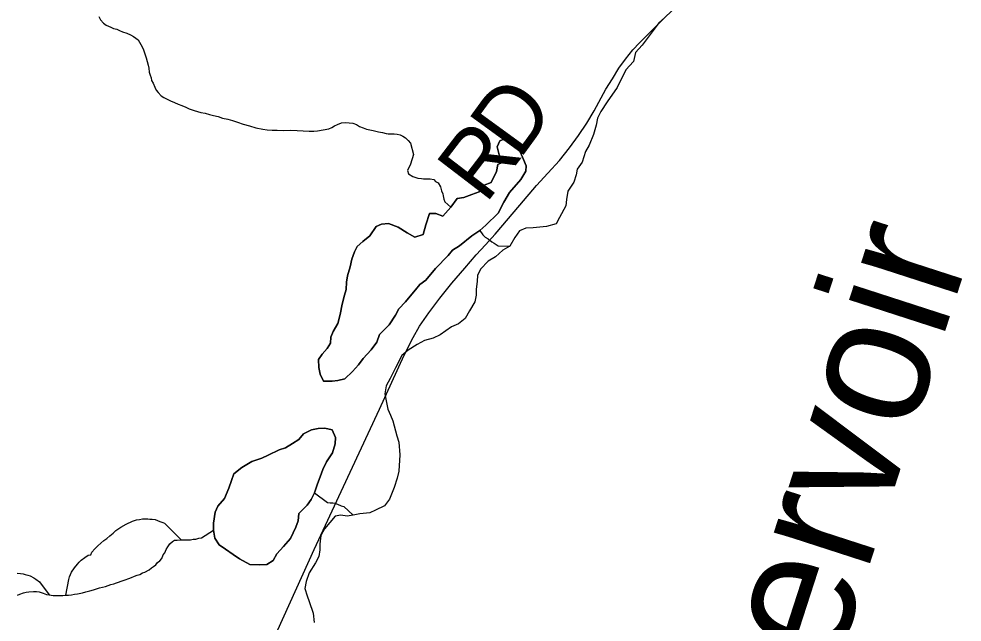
# Model space of a CAD drawing. Extents: x -10.1 to 68, y -9.5 to 29.2.
# Drawn here: x 5.518 to 6.333, y 19.95 to 20.471 of the extents above; entities that cross this region are included whole.
import ezdxf

# ---------------------------------------------------------------- set-up
doc = ezdxf.new("R2010")
doc.units = 0
for name, color, linetype in [('GM_X_Major_Lake', 7, 'Continuous'), ('GM_X_Major_Lake_Text', 7, 'Continuous'), ('GM_X_Major_River', 7, 'Continuous'), ('GM_X_Minor_Lake', 7, 'Continuous'), ('GM_X_Minor_River', 7, 'Continuous'), ('GM_X_Township_Road', 7, 'Continuous'), ('GM_X_Township_Road_Text', 7, 'Continuous')]:
    doc.layers.add(name, color=color, linetype=linetype)

msp = doc.modelspace()

# ---------------------------------------------------------------- linework, layer by layer
at = {"layer": 'GM_X_Major_Lake'}
for points in [[(6.07557, 20.47208), (6.07064, 20.4679), (6.06646, 20.46219), (6.05621, 20.44851), (6.05052, 20.44204), (6.04862, 20.43444), (6.04217, 20.42722), (6.03458, 20.41201), (6.02585, 20.39947), (6.02054, 20.3911), (6.0175, 20.3854), (6.01636, 20.37932), (6.01408, 20.37134), (6.01028, 20.36222), (6.00725, 20.35651), (6.00421, 20.34739), (6.00003, 20.34131), (5.99927, 20.33637), (5.997, 20.33029), (5.99206, 20.32231), (5.99092, 20.31509), (5.99016, 20.30977), (5.98485, 20.29951), (5.98181, 20.29418), (5.97346, 20.29189), (5.96777, 20.29113), (5.96208, 20.29074), (5.95563, 20.29035), (5.95032, 20.28807), (5.94614, 20.28236), (5.94197, 20.27476), (5.9359, 20.27133), (5.92945, 20.26563), (5.923, 20.26182), (5.91654, 20.25498), (5.91389, 20.24965), (5.91351, 20.24472), (5.91275, 20.2375), (5.91274, 20.23256), (5.9116, 20.22686), (5.90705, 20.21888), (5.90325, 20.21241), (5.89756, 20.20785), (5.89149, 20.20518), (5.88162, 20.19833), (5.87555, 20.19529), (5.86796, 20.19338), (5.86189, 20.18995), (5.85392, 20.18501), (5.84861, 20.18044), (5.84292, 20.16979), (5.83836, 20.16067), (5.83495, 20.15421), (5.83381, 20.14737), (5.83494, 20.14129), (5.83646, 20.13408), (5.83874, 20.12876), (5.84063, 20.12383), (5.84404, 20.11091), (5.84594, 20.1056), (5.84669, 20.09458), (5.84593, 20.08053), (5.84441, 20.07445), (5.84175, 20.06647), (5.83796, 20.0562), (5.8334, 20.0505), (5.82581, 20.04669), (5.82088, 20.04441), (5.81215, 20.04364), (5.80646, 20.04249), (5.80115, 20.04173), (5.79584, 20.04248), (5.79091, 20.04171), (5.7818, 20.03069), (5.77838, 20.02498), (5.77762, 20.01739), (5.77762, 20.01245), (5.77686, 20.00675), (5.77382, 20.00143), (5.76851, 19.99268), (5.76585, 19.98508), (5.76471, 19.979), (5.76661, 19.97293), (5.7685, 19.96799), (5.77192, 19.95774)], [(5.77192, 19.95774), (5.77267, 19.94976)]]:
    msp.add_lwpolyline(points, dxfattribs=at)
at = {"layer": 'GM_X_Major_River'}
for points in [[(6.07557, 20.47208), (6.07064, 20.4679), (6.06646, 20.46219), (6.05621, 20.44851), (6.05052, 20.44204), (6.04862, 20.43444), (6.04217, 20.42722), (6.03458, 20.41201), (6.02585, 20.39947), (6.02054, 20.3911), (6.0175, 20.3854), (6.01636, 20.37932), (6.01408, 20.37134), (6.01028, 20.36222), (6.00725, 20.35651), (6.00421, 20.34739), (6.00003, 20.34131), (5.99927, 20.33637), (5.997, 20.33029), (5.99206, 20.32231), (5.99092, 20.31509), (5.99016, 20.30977), (5.98485, 20.29951), (5.98181, 20.29418), (5.97346, 20.29189), (5.96777, 20.29113), (5.96208, 20.29074), (5.95563, 20.29035), (5.95032, 20.28807), (5.94614, 20.28236), (5.94197, 20.27476), (5.9359, 20.27133), (5.92945, 20.26563), (5.923, 20.26182), (5.91654, 20.25498), (5.91389, 20.24965), (5.91351, 20.24472), (5.91275, 20.2375), (5.91274, 20.23256), (5.9116, 20.22686), (5.90705, 20.21888), (5.90325, 20.21241), (5.89756, 20.20785), (5.89149, 20.20518), (5.88162, 20.19833), (5.87555, 20.19529), (5.86796, 20.19338), (5.86189, 20.18995), (5.85392, 20.18501), (5.84861, 20.18044), (5.84292, 20.16979), (5.83836, 20.16067), (5.83495, 20.15421), (5.83381, 20.14737), (5.83494, 20.14129), (5.83646, 20.13408), (5.83874, 20.12876), (5.84063, 20.12383), (5.84404, 20.11091), (5.84594, 20.1056), (5.84669, 20.09458), (5.84593, 20.08053), (5.84441, 20.07445), (5.84175, 20.06647), (5.83796, 20.0562), (5.8334, 20.0505), (5.82581, 20.04669), (5.82088, 20.04441), (5.81215, 20.04364), (5.80646, 20.04249), (5.80115, 20.04173), (5.79584, 20.04248), (5.79091, 20.04171), (5.7818, 20.03069), (5.77838, 20.02498), (5.77762, 20.01739), (5.77762, 20.01245), (5.77686, 20.00675), (5.77382, 20.00143), (5.76851, 19.99268), (5.76585, 19.98508), (5.76471, 19.979), (5.76661, 19.97293), (5.7685, 19.96799), (5.77192, 19.95774)], [(5.77192, 19.95774), (5.77267, 19.94976)]]:
    msp.add_lwpolyline(points, dxfattribs=at)
at = {"layer": 'GM_X_Minor_Lake'}
for points in [[(5.90896, 20.28384), (5.89834, 20.27509), (5.89227, 20.27128), (5.88847, 20.26672), (5.87746, 20.25569), (5.86912, 20.24542), (5.86418, 20.24162), (5.86039, 20.23706), (5.85583, 20.23173), (5.85166, 20.22679), (5.84596, 20.2207), (5.84293, 20.21538), (5.83761, 20.20702), (5.82927, 20.19865), (5.82699, 20.19181), (5.82205, 20.18535), (5.81522, 20.17774), (5.81105, 20.17242), (5.80574, 20.16671), (5.79928, 20.16025), (5.79321, 20.15872), (5.78828, 20.15833), (5.78069, 20.15833), (5.77804, 20.1644), (5.7769, 20.1701), (5.77652, 20.17694), (5.77956, 20.1815), (5.78411, 20.18644), (5.78677, 20.191), (5.78715, 20.19632), (5.78905, 20.20126), (5.79322, 20.20811), (5.79512, 20.21571), (5.79702, 20.22483), (5.79892, 20.23243), (5.80044, 20.23737), (5.80082, 20.24383), (5.80158, 20.24914), (5.80386, 20.25712), (5.80538, 20.26358), (5.80766, 20.27004), (5.80993, 20.27461), (5.81487, 20.27879), (5.82094, 20.28374), (5.82625, 20.29172), (5.83081, 20.294), (5.83688, 20.29439), (5.84522, 20.29136), (5.85319, 20.28643), (5.85964, 20.28264), (5.86685, 20.28493), (5.86913, 20.29329), (5.87254, 20.30317), (5.87786, 20.30318), (5.88392, 20.3009), (5.89076, 20.30851), (5.89645, 20.31611), (5.90214, 20.31688), (5.90897, 20.31955), (5.91542, 20.32184), (5.9196, 20.32754), (5.92567, 20.32983), (5.93022, 20.33933), (5.93136, 20.34541), (5.93592, 20.34731), (5.9325, 20.35377), (5.93099, 20.3606), (5.93327, 20.36592), (5.9382, 20.36783), (5.94503, 20.36404), (5.94996, 20.35835), (5.95375, 20.34961), (5.95602, 20.3443), (5.95564, 20.33974), (5.95147, 20.33251), (5.9416, 20.32111), (5.93667, 20.31274), (5.93173, 20.30324), (5.92111, 20.29297), (5.91579, 20.2884), (5.90896, 20.28384)], [(5.90896, 20.28384), (5.91579, 20.2884), (5.92111, 20.29297), (5.93173, 20.30324), (5.93667, 20.31274), (5.9416, 20.32111), (5.95147, 20.33251), (5.95564, 20.33974), (5.95602, 20.3443), (5.95375, 20.34961), (5.94996, 20.35835), (5.94503, 20.36404), (5.9382, 20.36783), (5.93327, 20.36592), (5.93099, 20.3606), (5.9325, 20.35377), (5.93592, 20.34731), (5.93136, 20.34541), (5.93022, 20.33933), (5.92567, 20.32983), (5.9196, 20.32754), (5.91542, 20.32184), (5.90897, 20.31955), (5.90214, 20.31688), (5.89645, 20.31611), (5.89076, 20.30851), (5.88392, 20.3009), (5.87786, 20.30318), (5.87254, 20.30317), (5.86913, 20.29329), (5.86685, 20.28493), (5.85964, 20.28264), (5.85319, 20.28643), (5.84522, 20.29136), (5.83688, 20.29439), (5.83081, 20.294), (5.82625, 20.29172), (5.82094, 20.28374), (5.81487, 20.27879), (5.80993, 20.27461), (5.80766, 20.27004)], [(5.80766, 20.27004), (5.80538, 20.26358), (5.80386, 20.25712), (5.80158, 20.24914), (5.80082, 20.24383), (5.80044, 20.23737), (5.79892, 20.23243), (5.79702, 20.22483), (5.79512, 20.21571), (5.79322, 20.20811), (5.78905, 20.20126), (5.78715, 20.19632), (5.78677, 20.191), (5.78411, 20.18644), (5.77956, 20.1815), (5.77652, 20.17694), (5.7769, 20.1701), (5.77804, 20.1644), (5.78069, 20.15833), (5.78828, 20.15833), (5.79321, 20.15872), (5.79928, 20.16025), (5.80574, 20.16671), (5.81105, 20.17242), (5.81522, 20.17774), (5.82205, 20.18535), (5.82699, 20.19181), (5.82927, 20.19865), (5.83761, 20.20702), (5.84293, 20.21538), (5.84596, 20.2207), (5.85166, 20.22679), (5.85583, 20.23173), (5.86039, 20.23706), (5.86418, 20.24162), (5.86912, 20.24542), (5.87746, 20.25569), (5.88847, 20.26672), (5.89227, 20.27128), (5.89834, 20.27509), (5.90896, 20.28384)], [(5.76663, 20.05118), (5.75942, 20.04396), (5.75903, 20.0375), (5.75676, 20.03218), (5.7522, 20.02229), (5.74613, 20.01545), (5.74044, 20.00898), (5.7374, 20.00328), (5.73171, 19.99986), (5.72564, 19.99947), (5.71729, 19.99984), (5.70819, 20.00477), (5.70288, 20.00856), (5.69605, 20.01311), (5.69074, 20.0169), (5.68694, 20.0226), (5.68581, 20.02944), (5.68581, 20.03551), (5.68733, 20.04501), (5.68961, 20.05033), (5.6953, 20.0568), (5.6991, 20.06592), (5.70137, 20.07238), (5.70327, 20.07808), (5.7101, 20.08379), (5.71883, 20.08874), (5.72756, 20.09179), (5.73287, 20.09445), (5.74236, 20.09902), (5.74805, 20.10055), (5.75412, 20.10435), (5.75943, 20.10778), (5.76361, 20.11272), (5.77044, 20.11615), (5.77613, 20.11729), (5.78182, 20.11768), (5.78827, 20.11617), (5.7913, 20.10971), (5.79092, 20.10402), (5.78864, 20.09641), (5.78333, 20.08843), (5.78029, 20.08197), (5.77802, 20.07551), (5.77574, 20.06943), (5.77308, 20.06183), (5.77004, 20.05612), (5.76663, 20.05118)], [(5.76663, 20.05118), (5.77004, 20.05612), (5.77308, 20.06183), (5.77574, 20.06943), (5.77802, 20.07551), (5.78029, 20.08197), (5.78333, 20.08843), (5.78864, 20.09641), (5.79092, 20.10402), (5.7913, 20.10971), (5.78827, 20.11617), (5.78182, 20.11768), (5.77613, 20.11729), (5.77044, 20.11615), (5.76361, 20.11272), (5.75943, 20.10778), (5.75412, 20.10435), (5.74805, 20.10055), (5.74236, 20.09902), (5.73287, 20.09445), (5.72756, 20.09179), (5.71883, 20.08874), (5.7101, 20.08379), (5.70327, 20.07808)], [(5.70327, 20.07808), (5.70137, 20.07238), (5.6991, 20.06592), (5.6953, 20.0568), (5.68961, 20.05033), (5.68733, 20.04501), (5.68581, 20.03551), (5.68581, 20.02944), (5.68694, 20.0226), (5.69074, 20.0169), (5.69605, 20.01311), (5.70288, 20.00856), (5.70819, 20.00477), (5.71729, 19.99984), (5.72564, 19.99947), (5.73171, 19.99986), (5.7374, 20.00328), (5.74044, 20.00898), (5.74613, 20.01545), (5.7522, 20.02229), (5.75676, 20.03218), (5.75903, 20.0375), (5.75942, 20.04396), (5.76663, 20.05118)]]:
    msp.add_lwpolyline(points, dxfattribs=at)
at = {"layer": 'GM_X_Minor_River'}
for points in [[(5.58663, 20.47325), (5.58822, 20.47024), (5.59056, 20.46763), (5.59288, 20.46578), (5.5971, 20.46397), (5.59941, 20.46288), (5.60208, 20.46218), (5.60439, 20.46109), (5.60708, 20.46001), (5.6109, 20.45895), (5.61398, 20.4575), (5.61667, 20.45604), (5.6186, 20.45456), (5.62054, 20.45308), (5.62409, 20.44708), (5.62528, 20.44444), (5.6265, 20.44105), (5.62771, 20.43766), (5.62855, 20.43425), (5.62937, 20.43123), (5.62981, 20.42858), (5.63026, 20.42517), (5.63108, 20.42253), (5.63189, 20.42026), (5.63232, 20.41799), (5.6335, 20.41574), (5.6351, 20.41235), (5.63629, 20.40972), (5.63786, 20.40747), (5.64058, 20.40487), (5.6429, 20.4034), (5.64559, 20.40194), (5.64867, 20.40049), (5.65212, 20.39904), (5.65519, 20.39759), (5.65826, 20.39651), (5.66171, 20.39507), (5.66479, 20.39362), (5.669, 20.39219), (5.67475, 20.39041), (5.67856, 20.38974), (5.68239, 20.38868), (5.68584, 20.38761), (5.68966, 20.38694), (5.69349, 20.3855), (5.69808, 20.38446), (5.70228, 20.38341), (5.7065, 20.38198), (5.71148, 20.38019), (5.71684, 20.37879), (5.7222, 20.37701), (5.72831, 20.376), (5.73213, 20.37532), (5.73632, 20.37503), (5.74088, 20.37513), (5.74583, 20.37486), (5.75192, 20.37499), (5.75801, 20.37474), (5.76334, 20.37448), (5.76829, 20.37421), (5.77247, 20.3743), (5.77551, 20.37436), (5.78537, 20.3761), (5.78801, 20.3773), (5.79025, 20.37887), (5.79289, 20.38006), (5.79629, 20.38128), (5.80008, 20.38174), (5.80313, 20.38143), (5.80618, 20.38111), (5.80925, 20.38004), (5.81195, 20.3782), (5.81502, 20.37712), (5.81808, 20.37605), (5.82382, 20.37466), (5.82841, 20.37361), (5.83184, 20.37293)], [(5.83184, 20.37293), (5.8349, 20.37224), (5.83681, 20.3719), (5.83909, 20.37195), (5.84175, 20.37201), (5.84442, 20.37169), (5.8471, 20.37098), (5.84941, 20.36989), (5.85172, 20.36842), (5.85405, 20.36619), (5.856, 20.36396), (5.85849, 20.35413), (5.85601, 20.34571), (5.85346, 20.34034), (5.85429, 20.33732), (5.85813, 20.33512), (5.86235, 20.33369), (5.8654, 20.33338), (5.86731, 20.33304), (5.87301, 20.33316), (5.87607, 20.33247), (5.87763, 20.3306), (5.87994, 20.32951), (5.88191, 20.32614), (5.88274, 20.32273), (5.88394, 20.3201), (5.88436, 20.31821), (5.8848, 20.31556), (5.88561, 20.31329), (5.89076, 20.30851)], [(5.91579, 20.2884), (5.91855, 20.28475), (5.9205, 20.28251), (5.92319, 20.28105), (5.92629, 20.27846), (5.92822, 20.27736), (5.93169, 20.27516), (5.94197, 20.27476)], [(5.77308, 20.06183), (5.78425, 20.05342), (5.78654, 20.05309), (5.78882, 20.05314), (5.79073, 20.0528), (5.79303, 20.05209), (5.7961, 20.05064), (5.7984, 20.04993), (5.80646, 20.04249)], [(5.5581, 19.97325), (5.56085, 19.98699), (5.56118, 19.98928), (5.563, 19.99312), (5.56558, 19.99698), (5.56818, 20.00008), (5.56966, 20.00201), (5.57153, 20.00357), (5.57452, 20.00591), (5.57752, 20.00788), (5.5798, 20.00831), (5.58051, 20.01061), (5.58311, 20.01332), (5.58572, 20.01604), (5.58833, 20.01838), (5.59094, 20.02071), (5.59357, 20.02229), (5.59618, 20.02463), (5.59918, 20.02697), (5.60141, 20.0293), (5.60554, 20.03205), (5.61042, 20.03482), (5.6157, 20.03721), (5.6191, 20.03843), (5.62175, 20.03886), (5.6244, 20.0393), (5.62668, 20.03935), (5.62897, 20.0394), (5.63087, 20.03906), (5.63277, 20.0391), (5.63545, 20.03878), (5.63929, 20.03697), (5.64197, 20.03626), (5.6435, 20.03554), (5.65788, 20.02103)], [(5.66587, 20.0212), (5.66814, 20.02163), (5.67042, 20.02168), (5.67307, 20.0225), (5.67534, 20.02293), (5.68581, 20.02944)], [(5.51625, 19.97348), (5.51851, 19.97429), (5.52153, 19.9755), (5.5238, 19.97593), (5.52608, 19.97636), (5.53026, 19.97645), (5.53292, 19.97651), (5.53521, 19.97618), (5.53866, 19.97511), (5.54134, 19.97403), (5.54363, 19.9737), (5.54707, 19.97301), (5.55049, 19.97309), (5.55315, 19.97315), (5.55544, 19.9732), (5.5581, 19.97325), (5.56038, 19.9733), (5.56303, 19.97374), (5.56568, 19.97418), (5.56834, 19.97462), (5.57251, 19.97547), (5.57553, 19.97629), (5.57894, 19.97713), (5.58196, 19.97795), (5.58461, 19.97877), (5.58725, 19.97959), (5.5899, 19.9804), (5.59255, 19.98084), (5.59482, 19.98165), (5.59708, 19.98246), (5.59973, 19.98328), (5.60199, 19.98409), (5.60766, 19.98611), (5.60955, 19.98653), (5.61257, 19.98774), (5.61483, 19.98855), (5.61747, 19.98975), (5.61974, 19.99055), (5.622, 19.99136), (5.62426, 19.99255), (5.62652, 19.99336), (5.63028, 19.99534), (5.63215, 19.9969), (5.63403, 19.99809), (5.6359, 19.99965), (5.63738, 20.00158), (5.63925, 20.00314), (5.64111, 20.00508), (5.64218, 20.00815), (5.64367, 20.01008), (5.64475, 20.01276), (5.64622, 20.01507), (5.64806, 20.01777), (5.65031, 20.01972), (5.65218, 20.0209), (5.65446, 20.02096), (5.65788, 20.02103), (5.66245, 20.02113), (5.66587, 20.0212)], [(5.51622, 19.99248), (5.51889, 19.99216), (5.52118, 19.99183), (5.5231, 19.99111), (5.52539, 19.99078), (5.52731, 19.99007), (5.53039, 19.98823), (5.53231, 19.98713), (5.53541, 19.98492), (5.54363, 19.9737)]]:
    msp.add_lwpolyline(points, dxfattribs=at)
at = {"layer": 'GM_X_Township_Road'}
for points in [[(6.05383, 20.45039), (6.05898, 20.45565), (6.09823, 20.4949), (6.12707, 20.52351), (6.14079, 20.53841), (6.14859, 20.54905), (6.15544, 20.55851), (6.16348, 20.57222), (6.16845, 20.58239), (6.17365, 20.59468), (6.17791, 20.60674), (6.18169, 20.62211), (6.18405, 20.6389), (6.18595, 20.65001), (6.18618, 20.66183), (6.18642, 20.672), (6.18666, 20.69163), (6.18666, 20.71834), (6.18476, 20.8848), (6.18465, 20.9)], [(5.72488, 19.90711), (5.77264, 20.0128), (5.82915, 20.13409), (5.85043, 20.18067), (5.85824, 20.19604), (5.86367, 20.20573), (5.87171, 20.21732), (5.88141, 20.22985), (5.89181, 20.24286), (5.90292, 20.25586), (5.91285, 20.26745), (5.92089, 20.27596), (5.92917, 20.28518), (5.95045, 20.31024), (5.96486, 20.32715), (5.97466, 20.33786), (5.98473, 20.34878), (5.99348, 20.3599), (6.00105, 20.37054), (6.00838, 20.38118), (6.01476, 20.39181), (6.02067, 20.40293), (6.02469, 20.41049), (6.0306, 20.41948), (6.03604, 20.4287), (6.04172, 20.43627), (6.0481, 20.44454), (6.05383, 20.45039)]]:
    msp.add_lwpolyline(points, dxfattribs=at)

# ---------------------------------------------------------------- texts
at = {"layer": 'GM_X_Major_Lake_Text'}
msp.add_text('Reservoir', height=0.11372, rotation=72.06558, dxfattribs=at).set_placement((6.14055, 19.65318))
at = {"layer": 'GM_X_Township_Road_Text'}
for s, rotation, p in [('D', 53.98076, (5.95004, 20.34869)), ('R', 52.56728, (5.92077, 20.31043))]:
    msp.add_text(s, height=0.05682, rotation=rotation, dxfattribs=at).set_placement(p)

doc.saveas('drawing.dxf')
